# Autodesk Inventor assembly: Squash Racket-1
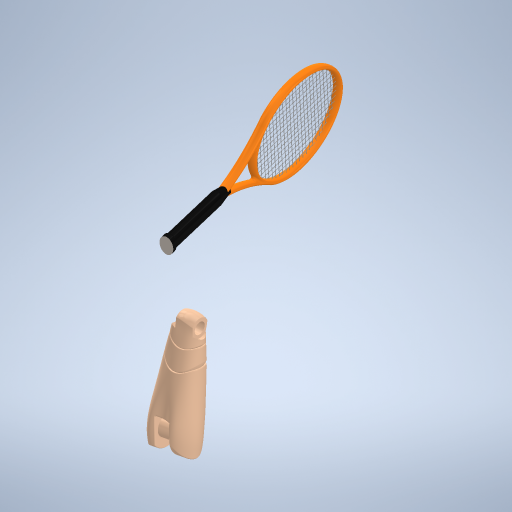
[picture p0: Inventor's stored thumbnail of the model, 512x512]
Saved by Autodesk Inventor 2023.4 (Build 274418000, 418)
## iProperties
Created: 2024-03
Part Number: Squash Racket-1
Material: Générique
Description: STEP AP214
Document SubType Name: Modeling
Designer: bruno
Density: 1 g/cm^3
Appearance: Par défaut
Title: Squash Racket-1.STEP
Revision Number: ANY
Sending System: SolidWorks 2018
Preprocessor: SwSTEP 2.0
Created: 2019-10
Part Number: Hand Full-tennis
Document SubType Name: Assembly
Designer: yello
Author: yello
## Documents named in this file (5)
- **C:\Users\bruno\Documents\1-Cours-2025-26\1STI2D\ETLV\Diversité et inclusion\Hand Full-tennis.iam*LocalDocs*xAaaaqwdaAaaaaaaaAaaaantwKa*Squash Racket-1.ipt
- C:\Users\bruno\Documents\1-Cours-2025-26\1STI2D\ETLV\Diversité et inclusion\Hand Full-tennis.iam
- C:\Users\bruno\Documents\1-Cours-2025-26\1STI2D\ETLV\Diversité et inclusion\Prototype 2 (Realistic Hand)\Wrist Rotation.ipt
- C:\Users\bruno\Documents\1-Cours-2025-26\1STI2D\ETLV\Diversité et inclusion\Prototype 2 (Realistic Hand)\Arm to Wrist Connection.ipt
- C:\Users\bruno\Documents\1-Cours-2025-26\1STI2D\ETLV\Diversité et inclusion\Prototype 2 (Realistic Hand)\Arm.ipt
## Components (4 placed, 4 different names)
1. Wrist Rotation:1 — Mate:1, Mate:2, Mate:4
2. Arm to Wrist Connection:1 — Mate:1, Mate:2, Mate:3
3. Arm:1 — Mate:3, Mate:4
4. Squash Racket-1:1
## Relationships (4: Mate 4)
- Mate:1: Wrist Rotation:1 ↔ Arm to Wrist Connection:1
- Mate:2: Wrist Rotation:1 ↔ Arm to Wrist Connection:1
- Mate:3: Arm to Wrist Connection:1 ↔ Arm:1
- Mate:4: Wrist Rotation:1 ↔ Arm:1
